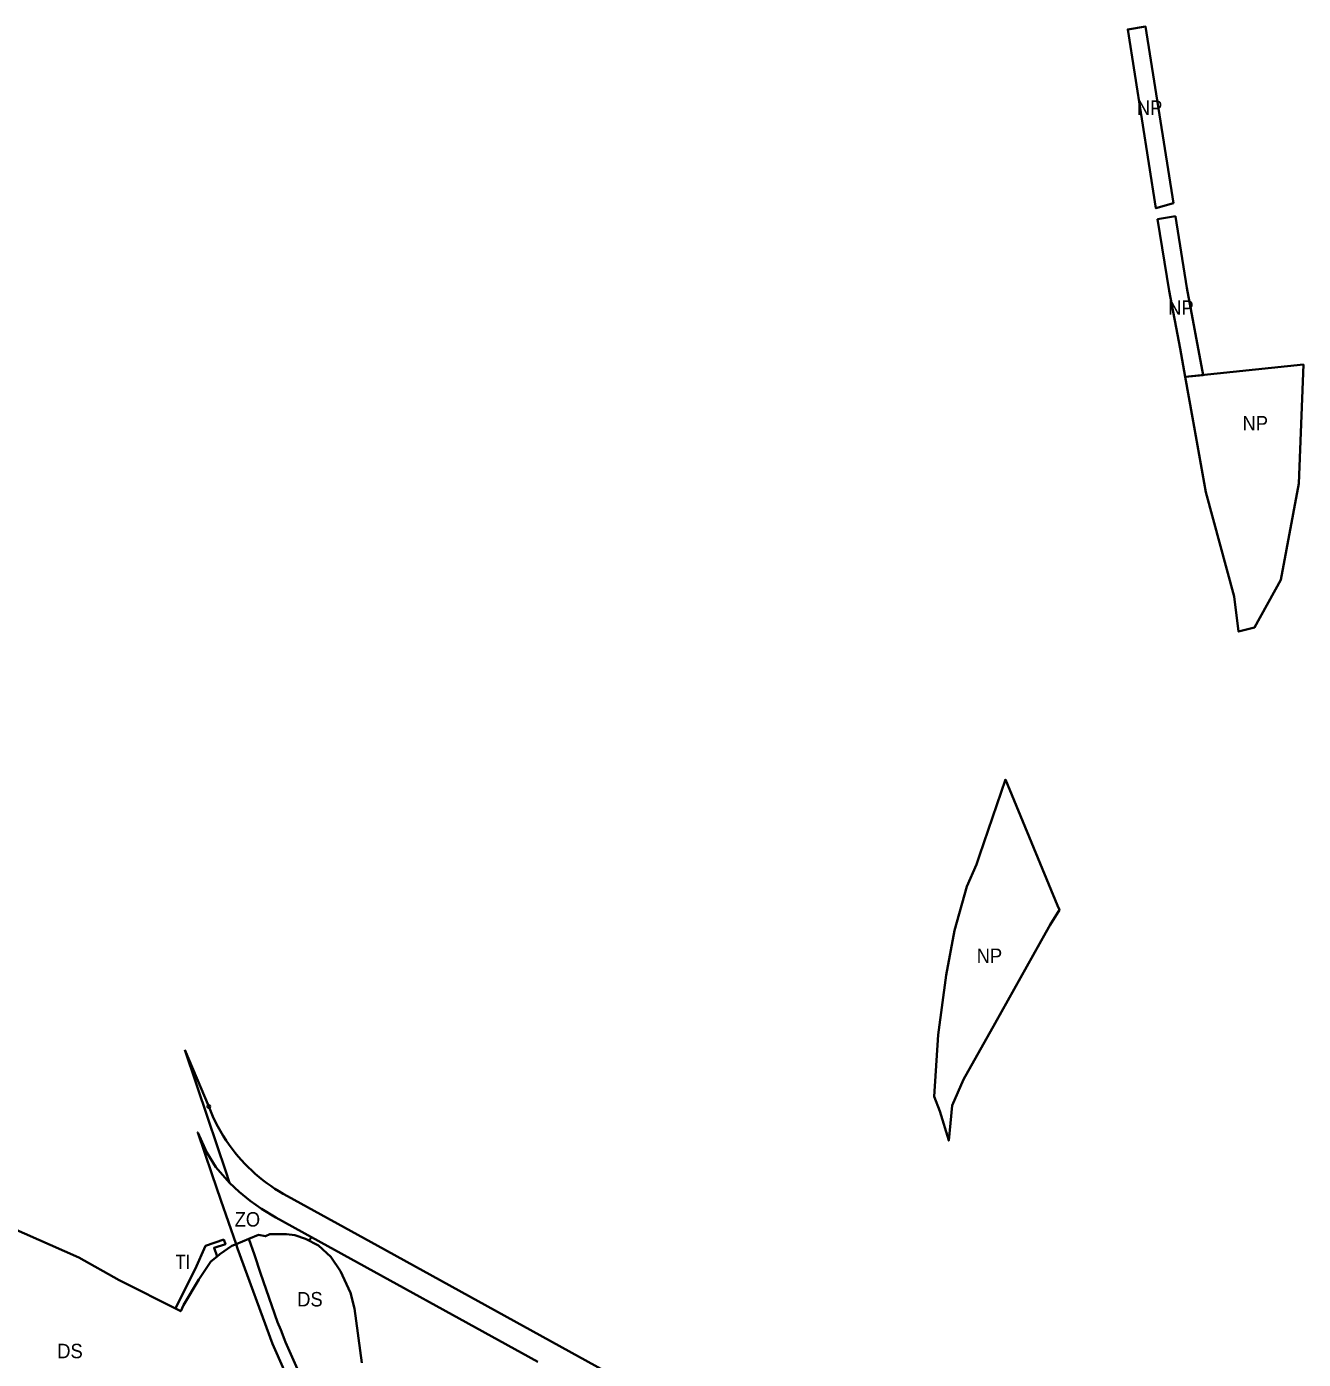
# Model space of a CAD drawing. Extents: x -650276 to -642489, y -1074311 to -1066720.
# Drawn here: x -646730 to -645670, y -1068611 to -1067505 of the extents above; entities that cross this region are included whole.
import ezdxf

# ---------------------------------------------------------------- set-up
doc = ezdxf.new("R2010")
doc.units = 0
doc.header["$LTSCALE"] = 4.8
doc.header["$PDMODE"] = 32
doc.header["$PDSIZE"] = 2.4
for name, color, linetype, lineweight in [('24', 7, 'Continuous', 35), ('30', 7, 'Continuous', 35), ('42', 7, 'Continuous', 35), ('48', 7, 'Continuous', 35)]:
    doc.layers.add(name, color=color, linetype=linetype, lineweight=lineweight)
doc.layers.add('62', color=7, linetype='Continuous')

msp = doc.modelspace()

# ---------------------------------------------------------------- linework, layer by layer
at = {"layer": '24'}
msp.add_line((-646578.881, -1068401.54), (-646598.635, -1068354.436), dxfattribs=at)
msp.add_line((-646578.881, -1068401.54), (-646598.635, -1068354.436), dxfattribs=at)
for points in [[(-646598.635, -1068354.436), (-646579.62, -1068411.29), (-646564.78, -1068455.41), (-646561.544, -1068464.842)], [(-646598.635, -1068354.436), (-646579.62, -1068411.29), (-646564.78, -1068455.41), (-646561.544, -1068464.842)], [(-646561.544, -1068464.842), (-646553.677, -1068472.283), (-646544.525, -1068479.79), (-646535.245, -1068486.342), (-646523.105, -1068493.54), (-646493.511, -1068509.855), (-646305.678, -1068613.404)], [(-646561.544, -1068464.842), (-646553.677, -1068472.283), (-646544.525, -1068479.79), (-646535.245, -1068486.342), (-646523.105, -1068493.54), (-646493.511, -1068509.855), (-646305.678, -1068613.404)], [(-646234.342, -1068629.893), (-646234.342, -1068629.892), (-646438.626, -1068517.274), (-646513.45, -1068476.025), (-646513.567, -1068475.963)], [(-646234.342, -1068629.893), (-646234.342, -1068629.892), (-646438.626, -1068517.274), (-646513.45, -1068476.025), (-646513.567, -1068475.963)], [(-646486.23, -1068688.54), (-646526.1, -1068598.55), (-646555, -1068519.38), (-646555, -1068519.38), (-646556.22, -1068515.84), (-646559.72, -1068517.29), (-646569.61, -1068524.1), (-646572.02, -1068526.07), (-646577.07, -1068530.2), (-646587.28, -1068545.28), (-646599.75, -1068566.49), (-646602.21, -1068571.5), (-646606.59, -1068569.33), (-646620.94, -1068561.96), (-646625.86, -1068559.47), (-646631.18, -1068556.77), (-646653.21, -1068545.58), (-646686.84, -1068526.89), (-646686.84, -1068526.89), (-646743.69, -1068501.76)], [(-646451.82, -1068614.31), (-646458.03, -1068569.26), (-646461.14, -1068556.34), (-646469.51, -1068538.15), (-646477.41, -1068526.45), (-646487.92, -1068516.87), (-646498.48, -1068511.26), (-646507.4, -1068508.45), (-646514.39, -1068507.56), (-646528.18, -1068507.58), (-646531.9, -1068509.25), (-646537.71, -1068508.16), (-646545.57, -1068511.42), (-646541.06, -1068524.58), (-646535.84, -1068539.8), (-646521.81, -1068580.69), (-646519.14, -1068587.06), (-646516.07, -1068595.08), (-646515.09, -1068597.29), (-646470.65, -1068697.38)]]:
    msp.add_lwpolyline(points, dxfattribs=at)
for start, end in [(200.6496, 215.36619), (200.64975, 215.36619), (215.36631, 241.891), (215.36642, 241.891)]:
    msp.add_arc((-646447.332, -1068351.964), 140.58, start, end, dxfattribs=at)
msp.add_point((-646578.881, -1068401.54), dxfattribs=at)
at = {"layer": '30'}
for points in [[(-646566.33, -1068512.04), (-646581.64, -1068517.24), (-646590.31, -1068536.69), (-646602.01, -1068560.15), (-646606.59, -1068569.33)], [(-646587.28, -1068545.28), (-646577.07, -1068530.2), (-646572.02, -1068526.07), (-646574.48, -1068518.75), (-646565.04, -1068515.86), (-646566.33, -1068512.04)], [(-646599.75, -1068566.49), (-646587.28, -1068545.28), (-646587.28, -1068545.28)], [(-646606.59, -1068569.33), (-646602.21, -1068571.5), (-646599.75, -1068566.49)]]:
    msp.add_lwpolyline(points, dxfattribs=at)
at = {"layer": '42'}
for points in [[(-646561.544, -1068464.842), (-646572.984, -1068451.81), (-646580.625, -1068439.803), (-646588.07, -1068422.96), (-646576.4, -1068457.27), (-646568.87, -1068479.14), (-646556.22, -1068515.84), (-646545.57, -1068511.42), (-646537.71, -1068508.16)], [(-646523.105, -1068493.54), (-646535.245, -1068486.342), (-646544.525, -1068479.79), (-646553.677, -1068472.283), (-646561.544, -1068464.842)], [(-646537.71, -1068508.16), (-646531.9, -1068509.25), (-646528.18, -1068507.58), (-646514.39, -1068507.56), (-646507.4, -1068508.45), (-646498.48, -1068511.26), (-646495.416, -1068512.888), (-646493.511, -1068509.855), (-646523.105, -1068493.54)]]:
    msp.add_lwpolyline(points, dxfattribs=at)
at = {"layer": '48'}
msp.add_line((-645750.9, -1067891.28), (-645727.57, -1067977.8), dxfattribs=at)
for points in [[(-645777.964, -1067651.174), (-645801.099, -1067504.689), (-645815.918, -1067507.016), (-645792.473, -1067655.466)], [(-645776.256, -1067661.991), (-645791.03, -1067664.6), (-645781.54, -1067724.05), (-645772.36, -1067771.99), (-645768.11, -1067795.54), (-645753.14, -1067793.982), (-645766.76, -1067721.483), (-645776.216, -1067662.248)], [(-645874.15, -1068234.44), (-645917.44, -1068129.99), (-645938.87, -1068193.06), (-645941.41, -1068200.54), (-645949.52, -1068218.72), (-645959.76, -1068255.23), (-645966.56, -1068292.38), (-645973.25, -1068342.08), (-645976.63, -1068393.14), (-645971.94, -1068405.38), (-645964.53, -1068429.83), (-645963.12, -1068415.21), (-645961.7, -1068400.54), (-645952.21, -1068378.95), (-645926.06, -1068332.18), (-645883.87, -1068256.88), (-645880.28, -1068250.47), (-645872.64, -1068238.08)]]:
    msp.add_lwpolyline(points, close=True, dxfattribs=at)
msp.add_lwpolyline([(-645727.57, -1067977.8), (-645723.79, -1068007.07), (-645710.519, -1068003.601), (-645688.88, -1067964.087), (-645673.827, -1067884.119), (-645670.064, -1067785.335), (-645768.11, -1067795.54), (-645762.15, -1067829.17), (-645750.9, -1067891.28)], dxfattribs=at)

# ---------------------------------------------------------------- texts
at = {"layer": '62'}
for s, width, p in [('NP', 0.95, (-645808.298, -1067578)), ('NP', 0.95, (-645782.298, -1067744)), ('NP', 0.95, (-645720.583, -1067840.041)), ('NP', 0.95, (-645941.298, -1068282.326)), ('ZO', 0.95, (-646557.423, -1068501.188)), ('TI', 0.85, (-646606.476, -1068536.535)), ('DS', 0.95, (-646505.476, -1068567.535)), ('DS', 0.95, (-646704.709, -1068610.535))]:
    msp.add_text(s, height=12, dxfattribs=dict(at, width=width)).set_placement(p)

doc.saveas('drawing.dxf')
